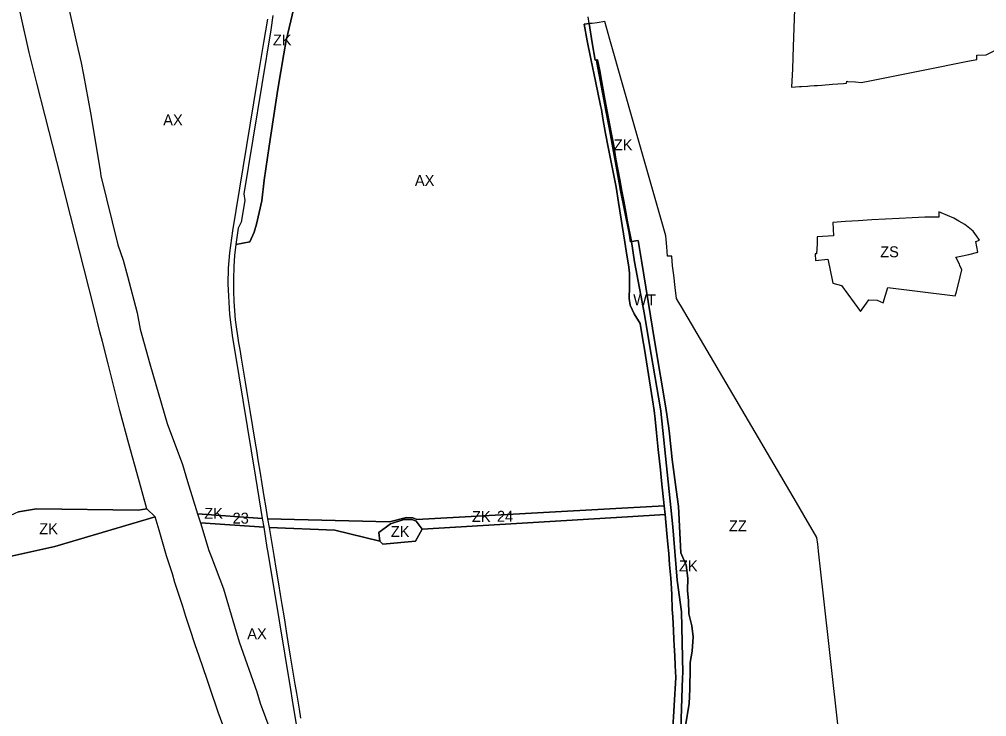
# Model space of a CAD drawing. Extents: x -521939 to -516426, y -1197857 to -1189551.
# Drawn here: x -520821 to -519936, y -1191694 to -1191056 of the extents above; entities that cross this region are included whole.
import ezdxf

# ---------------------------------------------------------------- set-up
doc = ezdxf.new("R2010")
doc.units = 0
for name, color, linetype in [('90640013', 7, 'Continuous'), ('90660013', 7, 'Continuous'), ('90670013', 7, 'Continuous'), ('90710013', 7, 'Continuous'), ('90710023', 7, 'Continuous'), ('90750013', 7, 'Continuous'), ('90760013', 7, 'Continuous'), ('ID_navrh', 7, 'Continuous')]:
    doc.layers.add(name, color=color, linetype=linetype)

msp = doc.modelspace()

# ---------------------------------------------------------------- linework, layer by layer
at = {"layer": '90640013'}
for points in [[(-520261.24, -1191259.2), (-520261.99, -1191259.34), (-520263.45, -1191251.6), (-520271.42, -1191211.02), (-520271.77, -1191208.88), (-520281.74, -1191154.92), (-520284.92, -1191137.88), (-520285.69, -1191134.05), (-520292.76, -1191095.53), (-520293.14, -1191093.08), (-520294.52, -1191093.34), (-520297.01, -1191077.41), (-520299.9, -1191059.72), (-520304.47, -1191060.46), (-520301.69, -1191075.49), (-520298.16, -1191093.68), (-520294.23, -1191112.48), (-520289.55, -1191134.71), (-520288.59, -1191138.42), (-520287.44, -1191146.61), (-520284.86, -1191160.34), (-520282.46, -1191172.67), (-520280.02, -1191185.03), (-520275.21, -1191209.44), (-520273.07, -1191223.41), (-520267.14, -1191259.68), (-520266.56, -1191263.57), (-520265.96, -1191267.74), (-520263.76, -1191282.48), (-520262.97, -1191288.13), (-520263, -1191289.81), (-520263.1, -1191300.43), (-520263.36, -1191311.23), (-520262.5, -1191317.25), (-520258.63, -1191325.14), (-520253.17, -1191334.19), (-520251.05, -1191347.07), (-520249.39, -1191357.72), (-520242.02, -1191403.91), (-520240.46, -1191413.62), (-520239.64, -1191421.72), (-520238.32, -1191434.21), (-520236.92, -1191449.23), (-520234.77, -1191468.04), (-520233.76, -1191477.92), (-520231.3, -1191500.76), (-520230.44, -1191508.92), (-520228.76, -1191526.15), (-520227.87, -1191535.88), (-520227.13, -1191544.34), (-520226.27, -1191554.72), (-520225.18, -1191567.05), (-520224.68, -1191576.39), (-520224.38, -1191582.34), (-520223.82, -1191595.58), (-520223.47, -1191602.38), (-520222.81, -1191614.77), (-520222.3, -1191623.25), (-520222.1, -1191628.59), (-520221.55, -1191638.06), (-520221.15, -1191646.84), (-520220.67, -1191658.04), (-520225.31, -1191734.79)], [(-520216.83, -1191733.94), (-520214.6, -1191657.89), (-520214.31, -1191653.49), (-520215.5, -1191597.95), (-520219.31, -1191568.84), (-520223.45, -1191520.14), (-520234.37, -1191414.4), (-520234.74, -1191412.31), (-520244.97, -1191351.93), (-520249.38, -1191325.86), (-520258.47, -1191277.73), (-520261.24, -1191259.2)]]:
    msp.add_lwpolyline(points, dxfattribs=at)
at = {"layer": '90660013'}
msp.add_lwpolyline([(-520030.97, -1191315.16), (-520026.6, -1191301.25), (-519964.93, -1191308.81), (-519963.94, -1191305.25), (-519960.36, -1191291.37), (-519958.82, -1191284.98), (-519960.73, -1191281.08), (-519961.11, -1191279.99), (-519964.43, -1191273.38), (-519959.74, -1191272.5), (-519952.61, -1191271.14), (-519944.27, -1191268.71), (-519946.16, -1191259.22), (-519942.81, -1191257.91), (-519943.38, -1191257.08), (-519945.48, -1191254.04), (-519948.47, -1191249.7), (-519956.25, -1191243.54), (-519961.54, -1191240.51), (-519966.22, -1191237.82), (-519977.75, -1191232.89), (-519979.96, -1191231.95), (-519980.06, -1191236.97), (-519992.69, -1191236.79), (-520004.24, -1191237.42), (-520016.18, -1191238.07), (-520028.72, -1191238.75), (-520041.26, -1191239.43), (-520053.81, -1191240.11), (-520065.31, -1191240.74), (-520076.92, -1191241.84), (-520076.38, -1191254.05), (-520091.17, -1191254.77), (-520091.31, -1191261.34), (-520092.05, -1191270.43), (-520092.99, -1191270.45), (-520092.81, -1191276.37), (-520081.63, -1191275.29), (-520080.09, -1191282.4), (-520076.9, -1191297.08), (-520068.94, -1191299.47), (-520051.66, -1191323.03), (-520046.15, -1191315.41), (-520044.01, -1191312.35), (-520036.39, -1191312.9), (-520030.97, -1191315.16)], dxfattribs=at)
at = {"layer": '90670013'}
for points in [[(-520111.98, -1191046.9), (-520113.12, -1191080.75), (-520113.89, -1191101.12), (-520114.81, -1191117.86), (-520107.55, -1191117.35), (-520105.6, -1191117.23), (-520100.16, -1191116.88), (-520098.03, -1191116.74), (-520094.01, -1191116.49), (-520091.05, -1191116.3), (-520087.14, -1191116.05), (-520084.05, -1191115.86), (-520080.18, -1191115.54), (-520077.33, -1191115.31), (-520072.53, -1191114.93), (-520067.33, -1191114.51), (-520064.41, -1191114.38), (-520064.3, -1191112.58), (-520063.61, -1191112.63), (-520056.23, -1191113.21), (-520051.04, -1191113.61), (-520043.16, -1191112.04), (-519994.2, -1191102.28), (-519953.42, -1191094.16), (-519945.25, -1191092.53), (-519945.23, -1191092.53), (-519945.15, -1191088.6), (-519936.67, -1191088.33), (-519911.75, -1191075.87)], [(-520070.57, -1191717.02), (-520080.29, -1191629.67), (-520088.79, -1191553.34), (-520090.01, -1191542.33), (-520090.06, -1191541.94), (-520090.81, -1191535.95), (-520091.57, -1191529.97), (-520103.62, -1191509.45), (-520110.36, -1191497.96), (-520215.49, -1191318.85), (-520217.72, -1191315.04), (-520219.96, -1191311.24), (-520221.12, -1191301.15), (-520222.31, -1191289.84), (-520223.61, -1191281.32), (-520224.29, -1191272.4), (-520228.29, -1191272.51), (-520228.7, -1191264.03), (-520229.8, -1191253.95), (-520257.67, -1191155.89), (-520280.88, -1191074.27), (-520285.55, -1191057.83), (-520292.62, -1191059.21), (-520297.2, -1191059.84), (-520299.9, -1191059.72), (-520297.01, -1191077.41), (-520294.52, -1191093.34), (-520293.14, -1191093.08), (-520292.41, -1191092.95), (-520290.16, -1191102.93), (-520288.49, -1191111.75), (-520287.01, -1191120.32), (-520285.46, -1191129.01), (-520282.21, -1191146.62), (-520279.86, -1191159.32), (-520277.49, -1191171.73), (-520275.42, -1191183.89), (-520271.92, -1191202.62), (-520269.99, -1191212.97), (-520268.24, -1191222.34), (-520266.38, -1191232.16), (-520264.7, -1191240.97), (-520261.24, -1191259.2)], [(-520261.24, -1191259.2), (-520255.13, -1191258.18), (-520252.09, -1191276.62), (-520239.71, -1191351.51), (-520229.82, -1191411.39), (-520227, -1191429.8), (-520226.35, -1191435.06), (-520224.05, -1191458.56), (-520220.35, -1191485.89), (-520218.25, -1191501.38), (-520216.62, -1191531.81), (-520216.07, -1191543.85), (-520211.08, -1191555.16), (-520209.53, -1191567.09), (-520209.99, -1191578.18), (-520208.97, -1191587.71), (-520208.64, -1191599.6), (-520205.92, -1191610.73), (-520204.9, -1191620.82), (-520205.7, -1191633.82), (-520207.63, -1191644.33), (-520207.57, -1191648.86), (-520207.67, -1191668.69), (-520208.37, -1191681.55), (-520211.37, -1191700.36)]]:
    msp.add_lwpolyline(points, dxfattribs=at)
at = {"layer": '90710013'}
for points in [[(-520623.25, -1191261.94), (-520610.45, -1191259.33), (-520606.28, -1191250.57), (-520604.31, -1191243.32), (-520599.39, -1191221.99), (-520597.13, -1191202.86), (-520592.81, -1191171.76), (-520584.87, -1191119.79), (-520579.12, -1191087.48), (-520577.05, -1191075.31), (-520570.23, -1191045.78)], [(-520589.24, -1191052.36), (-520591.05, -1191065.64), (-520615.94, -1191215.64), (-520614.89, -1191221.55), (-520618.19, -1191241.45), (-520621.13, -1191246.77), (-520623.25, -1191261.94)], [(-520261.24, -1191259.2), (-520264.7, -1191240.97), (-520266.38, -1191232.16), (-520268.24, -1191222.34), (-520269.99, -1191212.97), (-520271.92, -1191202.62), (-520275.42, -1191183.89), (-520277.49, -1191171.73), (-520279.86, -1191159.32), (-520282.21, -1191146.62), (-520285.46, -1191129.01), (-520287.01, -1191120.32), (-520288.49, -1191111.75), (-520290.16, -1191102.93), (-520292.41, -1191092.95), (-520293.14, -1191093.08), (-520292.76, -1191095.53), (-520285.69, -1191134.05), (-520284.92, -1191137.88), (-520281.74, -1191154.92), (-520271.77, -1191208.88), (-520271.42, -1191211.02), (-520263.45, -1191251.6), (-520261.99, -1191259.34), (-520261.24, -1191259.2)], [(-520211.37, -1191700.36), (-520208.37, -1191681.55), (-520207.67, -1191668.69), (-520207.57, -1191648.86), (-520207.63, -1191644.33), (-520205.7, -1191633.82), (-520204.9, -1191620.82), (-520205.92, -1191610.73), (-520208.64, -1191599.6), (-520208.97, -1191587.71), (-520209.99, -1191578.18), (-520209.53, -1191567.09), (-520211.08, -1191555.16), (-520216.07, -1191543.85), (-520216.62, -1191531.81), (-520218.25, -1191501.38), (-520220.35, -1191485.89), (-520224.05, -1191458.56), (-520226.35, -1191435.06), (-520227, -1191429.8), (-520229.82, -1191411.39), (-520239.71, -1191351.51), (-520252.09, -1191276.62), (-520255.13, -1191258.18), (-520261.24, -1191259.2)], [(-520261.24, -1191259.2), (-520258.47, -1191277.73), (-520249.38, -1191325.86), (-520244.97, -1191351.93), (-520234.74, -1191412.31), (-520234.37, -1191414.4), (-520223.45, -1191520.14), (-520219.31, -1191568.84), (-520215.5, -1191597.95), (-520214.31, -1191653.49), (-520214.6, -1191657.89), (-520216.83, -1191733.94)], [(-520697.13, -1191510.79), (-520704.46, -1191503.52), (-520712.59, -1191504.94), (-520805.54, -1191503.53), (-520822.16, -1191506.38), (-520838.02, -1191513.71), (-520857.48, -1191545.13), (-520854.89, -1191552.76), (-520788.93, -1191537.99), (-520697.13, -1191510.79)], [(-520452.73, -1191522.22), (-520458.29, -1191515), (-520461.73, -1191513.47), (-520469.32, -1191513.47), (-520481.62, -1191517.42), (-520492.29, -1191525.29), (-520491.32, -1191533.14), (-520488.78, -1191536.08), (-520458.76, -1191533.25), (-520452.73, -1191522.22)]]:
    msp.add_lwpolyline(points, dxfattribs=at)
at = {"layer": '90710023'}
for points in [[(-520452.73, -1191522.22), (-520264.87, -1191510.98), (-520230.44, -1191508.92), (-520231.3, -1191500.76), (-520281.01, -1191503.56), (-520457.48, -1191513.5), (-520461.23, -1191511.82), (-520467.01, -1191511.47), (-520482.44, -1191515.66), (-520594.1, -1191512.73), (-520592.74, -1191520.81), (-520532.56, -1191523.11), (-520491.32, -1191533.14), (-520492.29, -1191525.29), (-520481.62, -1191517.42), (-520469.32, -1191513.47), (-520461.73, -1191513.47), (-520458.29, -1191515), (-520452.73, -1191522.22)], [(-520598.71, -1191512.42), (-520658.4, -1191508.21), (-520656.53, -1191513.73), (-520655.62, -1191516.43), (-520597.37, -1191520.53), (-520598.71, -1191512.42)]]:
    msp.add_lwpolyline(points, dxfattribs=at)
at = {"layer": '90750013'}
msp.add_lwpolyline([(-520632.82, -1191707.09), (-520639.25, -1191689.54), (-520646.67, -1191667.99), (-520649.42, -1191659.64), (-520656.86, -1191638.41), (-520660.4, -1191628.12), (-520665.33, -1191613.04), (-520668.87, -1191602.22), (-520671.8, -1191593.01), (-520678.86, -1191570.86), (-520681.21, -1191563.06), (-520686.61, -1191546.52), (-520693.46, -1191523.23), (-520697.13, -1191510.79), (-520788.93, -1191537.99), (-520854.89, -1191552.76)], dxfattribs=at)
at = {"layer": '90760013'}
for points in [[(-520704.46, -1191503.52), (-520712.23, -1191475.88), (-520721.14, -1191444.12), (-520729.17, -1191413.61), (-520732.39, -1191401.49), (-520740.08, -1191370.95), (-520745.31, -1191350.43), (-520747.53, -1191341.72), (-520752.93, -1191320.48), (-520762.01, -1191284.51), (-520774.39, -1191235.28), (-520786.96, -1191185.86), (-520797.61, -1191144.17), (-520805.2, -1191114.16), (-520812.23, -1191086.24), (-520820.01, -1191052.05), (-520822.58, -1191039.85)], [(-520776.73, -1191043.11), (-520769.65, -1191074.63), (-520764.59, -1191095.68), (-520762.68, -1191106.73), (-520756.19, -1191141.57), (-520747.26, -1191194.03), (-520746.79, -1191199.07), (-520731.29, -1191262.08), (-520728.77, -1191269.08), (-520726.33, -1191276.25), (-520722.32, -1191290.79), (-520713.4, -1191324.5), (-520710.85, -1191339.33), (-520701.83, -1191371.04), (-520686.01, -1191425.6), (-520672.11, -1191463.11), (-520667.4, -1191478.56), (-520658.4, -1191508.21), (-520598.71, -1191512.42)], [(-520570.23, -1191045.78), (-520577.05, -1191075.31), (-520579.12, -1191087.48), (-520584.87, -1191119.79), (-520592.81, -1191171.76), (-520597.13, -1191202.86), (-520599.39, -1191221.99), (-520604.31, -1191243.32), (-520606.28, -1191250.57), (-520610.45, -1191259.33), (-520623.25, -1191261.94), (-520624.38, -1191271.96), (-520625.11, -1191281.97), (-520625.38, -1191293.53), (-520625.36, -1191304.16), (-520625.07, -1191313.94), (-520623.65, -1191330.68), (-520620.71, -1191351.68), (-520619.6, -1191358.04), (-520618.35, -1191365.76), (-520614.72, -1191387.87), (-520613.42, -1191395.5), (-520611.93, -1191404.62), (-520610.43, -1191413.76), (-520605.54, -1191443.5), (-520604.41, -1191450.26), (-520603, -1191458.86), (-520601.01, -1191470.86), (-520599.4, -1191480.74), (-520597.47, -1191492.24), (-520596.04, -1191500.86), (-520594.1, -1191512.73), (-520482.44, -1191515.66), (-520467.01, -1191511.47), (-520461.23, -1191511.82), (-520457.48, -1191513.5), (-520281.01, -1191503.56), (-520231.3, -1191500.76), (-520233.76, -1191477.92), (-520234.77, -1191468.04), (-520236.92, -1191449.23), (-520238.32, -1191434.21), (-520239.64, -1191421.72), (-520240.46, -1191413.62), (-520242.02, -1191403.91), (-520249.39, -1191357.72), (-520251.05, -1191347.07), (-520253.17, -1191334.19), (-520258.63, -1191325.14), (-520262.5, -1191317.25), (-520263.36, -1191311.23), (-520263.1, -1191300.43), (-520263, -1191289.81), (-520262.97, -1191288.13), (-520263.76, -1191282.48), (-520265.96, -1191267.74), (-520266.56, -1191263.57), (-520267.14, -1191259.68), (-520273.07, -1191223.41), (-520275.21, -1191209.44), (-520280.02, -1191185.03), (-520282.46, -1191172.67), (-520284.86, -1191160.34), (-520287.44, -1191146.61), (-520288.59, -1191138.42), (-520289.55, -1191134.71), (-520294.23, -1191112.48), (-520298.16, -1191093.68), (-520301.69, -1191075.49), (-520304.47, -1191060.46), (-520299.9, -1191059.72), (-520300.69, -1191053.74)], [(-520598.71, -1191512.42), (-520604.82, -1191474.76), (-520624.05, -1191357.94), (-520625.98, -1191347.07), (-520628.78, -1191326.02), (-520630.1, -1191297.74), (-520629.76, -1191283.58), (-520628.76, -1191269.45), (-520626.01, -1191249.41), (-520603.55, -1191113.81), (-520597.48, -1191077.12), (-520594.04, -1191055.69)], [(-520822.16, -1191506.38), (-520805.54, -1191503.53), (-520712.59, -1191504.94), (-520704.46, -1191503.52)], [(-520225.31, -1191734.79), (-520220.67, -1191658.04), (-520221.15, -1191646.84), (-520221.55, -1191638.06), (-520222.1, -1191628.59), (-520222.3, -1191623.25), (-520222.81, -1191614.77), (-520223.47, -1191602.38), (-520223.82, -1191595.58), (-520224.38, -1191582.34), (-520224.68, -1191576.39), (-520225.18, -1191567.05), (-520226.27, -1191554.72), (-520227.13, -1191544.34), (-520227.87, -1191535.88), (-520228.76, -1191526.15), (-520230.44, -1191508.92), (-520264.87, -1191510.98), (-520452.73, -1191522.22), (-520458.76, -1191533.25), (-520488.78, -1191536.08), (-520491.32, -1191533.14), (-520532.56, -1191523.11), (-520592.74, -1191520.81), (-520588.55, -1191546.35), (-520586.36, -1191559.62), (-520584.24, -1191572.29), (-520582.68, -1191582), (-520581.19, -1191591.03), (-520579.1, -1191603.39), (-520576.48, -1191619.53), (-520575.51, -1191625.38), (-520573.38, -1191638.42), (-520571.57, -1191649.5), (-520569.19, -1191663.93), (-520567.79, -1191672.26), (-520566.91, -1191677.66), (-520565.37, -1191686.86), (-520564, -1191695.24)], [(-520655.62, -1191516.43), (-520647.74, -1191541.74), (-520645.29, -1191547.71), (-520634.42, -1191576.76), (-520624.44, -1191610.86), (-520620.11, -1191625.25), (-520604.04, -1191671.07), (-520600.77, -1191681.45), (-520567.63, -1191770.59), (-520558.71, -1191767.21), (-520562, -1191747.31), (-520560.94, -1191741.4), (-520571.31, -1191678.64), (-520572.92, -1191668.76), (-520583.24, -1191606.18), (-520593.47, -1191543.67), (-520594.55, -1191539), (-520597.37, -1191520.53), (-520655.62, -1191516.43)]]:
    msp.add_lwpolyline(points, dxfattribs=at)

# ---------------------------------------------------------------- texts
at = {"layer": '90640013'}
msp.add_text('WT', height=10, rotation=360, dxfattribs=at).set_placement((-520259.59, -1191317.4))
at = {"layer": '90660013'}
msp.add_text('ZS', height=10, dxfattribs=at).set_placement((-520033.63, -1191273.5))
at = {"layer": '90670013'}
msp.add_text('ZZ', height=10, rotation=360, dxfattribs=at).set_placement((-520171.96, -1191524.14))
at = {"layer": '90710013'}
for rotation, p in [(360, (-520589.27, -1191079.78)), (360, (-520277.42, -1191175.63)), (360, (-520803.04, -1191526.84)), (0, (-520481.4, -1191529.41)), (360, (-520217.73, -1191560.84))]:
    msp.add_text('ZK', height=10, rotation=rotation, dxfattribs=at).set_placement(p)
at = {"layer": '90710023'}
for p in [(-520652.04, -1191512.73), (-520407.13, -1191515.67)]:
    msp.add_text('ZK', height=10, rotation=360, dxfattribs=at).set_placement(p)
at = {"layer": '90760013'}
for rotation, p in [(0, (-520689.61, -1191152.89)), (360, (-520459.35, -1191208.25)), (360, (-520612.76, -1191622.87))]:
    msp.add_text('AX', height=10, rotation=rotation, dxfattribs=at).set_placement(p)
at = {"layer": 'ID_navrh'}
for s, p in [('24', (-520384.27, -1191515.44)), ('23', (-520626.15, -1191517.15))]:
    msp.add_text(s, height=10, rotation=0, dxfattribs=at).set_placement(p)

doc.saveas('drawing.dxf')
